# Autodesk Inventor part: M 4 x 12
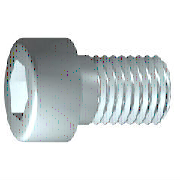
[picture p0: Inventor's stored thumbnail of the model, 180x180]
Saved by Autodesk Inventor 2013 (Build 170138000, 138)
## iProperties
IsCustomPart: 0
Created: 2009-02
Part Number: M 4 x 12
Material: 강, 연강
Description: 6각머리 태핑 나사
Document SubType Name: Modeling
Standard: KS B 1003
Designer: KYOUNG IL JANG
Standards Organization: KS
Language: ko-KR
Size Designation: M 4 x 12
Categories: <MemberInstance><Categories><Category DisplayName="조임쇠" InternalName="e4da775c-781d-43d5-af7c-5136215cf5a6" Mnemonic="FSTN"><Category DisplayName="볼트" InternalN
Density: 7.86 g/cm^3
Mass: 2.23465 g
Surface Area: 3.30853 cm^2
Volume: 0.284306 cm^3
Author: KYOUNG IL JANG
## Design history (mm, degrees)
sketch "스케치1"
  geometry: L1 (-1, 0)-(12, 0); L2 (12, 0)-(12, 2); L3 (12, 2)-(1.75, 2); L4 (1.75, 2)-(1.32, 2); L5 (1.32, 2)-(0, 2); L6 (0, 2)-(0, 3.5); L7 (0, 3.5)-(-4, 3.5); L8 (-4, 3.5)-(-4, 1.732); L9 (-4, 1.732)-(-2, 1.732); L10 (-2, 1.732)-(-1, 0); L11 (-7.2, 0)-(15.2, 0) reference; L12 (0, -0.7)-(0, 4.2) reference; L13 (1.75, 2)-(0, 2)
  constraints: 22 end point, 6 parallel, 2 collinear, 2 perpendicular, 1 horizontal, 1 point on line
  dimensions: "d1" = 10.25 distance from line of L3.end L2 (= GEL); "d2" = 0.42952 distance of L4.end L3.end (computed from GAL); "d3" = 4 distance between parallel lines of L8 L6 (= KOH); "d4" = 2 distance of L8.end L9.end (= INTI); "d5" = 60 deg angle of L10 L1; "d6" = 4 diameter of L3 L1 (= GD); "d7" = 4 diameter of L5 L1 (= BDM); "d8" = 3.4641 diameter of L9 L1 (= 1.1547 x SW); "d9" = 7 diameter of L7 L1 (= KOD); "d26" = 12 distance between parallel lines of L12 L2 (= NLG)
revolve "본체" sketch "스케치1" stored, may be unused: angle "d10" = 90 deg
sketch "스케치2"
  geometry: L1 (0, -4.9)-(0, 4.9) reference; L2 (-4.9, 0)-(4.9, 0) reference; L3 (1.732, 0)-(0.866, -1.5); L4 (0.866, -1.5)-(-0.866, -1.5); L5 (-0.866, -1.5)-(-1.732, 0); L6 (-1.732, 0)-(-0.866, 1.5); L7 (-0.866, 1.5)-(0.866, 1.5); L8 (0.866, 1.5)-(1.732, 0); 2 further points
  constraints: 12 end point, 1 coincident, 1 horizontal alignment, 1 point on line, 12 other
extrude "슬롯" join sketch "스케치2" stored distance "d11" = 10; taper "d12" = 0 deg
workplane "Work Plane1"
fillet "Fillet2" dims "d30" = 0.1 (= R)
body "Solid1"
fillet "모깎기1" dims "d17" = 0.4 (= RR)
feature "스레드" dims "d13" = 10.25 (= GEL), "d14" = 0
chamfer "모따기1" distance "d15" = 0.42941 (= -0.5 x SPD + 0.5 x GD); stored, may be unused: second distance "d16" = 0.42941 (= GUL), angle "d27" = 45 deg
other parameters: "GD" = 4 (= NND) [user parameter; used in 2 equation terms], "NLG" = 12 [user parameter; used in 1 equation term], "GEL" = 10.25 [user parameter; used in 2 equation terms], "KOD" = 7 [user parameter; used in 1 equation term], "KOH" = 4 [user parameter; used in 1 equation term], "INTI" = 2 [user parameter; used in 1 equation term], "GAL" = 0.42941 (= 0.61345 x PTC) [user parameter; used in 1 equation term], "GUL" = 0.42941 (= 0.61345 x PTC) [user parameter; used in 1 equation term], "BDM" = 4 (= NND) [user parameter; used in 1 equation term], "SW" = 3 [user parameter; used in 2 equation terms], "RR" = 0.4 [user parameter; used in 1 equation term], "SPD" = 3.14117 (= NND - 1.2269 x PTC) [user parameter; used in 1 equation term], "d19" = 0, "d28" = 0, "d29" = 0, "R" = 0.1 [user parameter; used in 1 equation term], "PHH" = 0.2 [user parameter], "GD1" = 3.14117 (= THREADDIA - 1.2269 x PTC) [user parameter], "THREADDIA" = 4 [user parameter; used in 1 equation term], "FAWI" = 45 deg [user parameter], "TPU" = 14.28571 (computed from PTC) [user parameter], "PTC" = 0.7 [user parameter; used in 5 equation terms], "NND" = 4 [user parameter; used in 3 equation terms], "TOA" = 30 deg [user parameter], "E0" = 3.465 (= 1.155 x SW) [user parameter]
